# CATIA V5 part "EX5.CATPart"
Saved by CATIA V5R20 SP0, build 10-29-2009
Part number: EX5
Bounding box of the stored display mesh (mm): x -50 to 70, y -49.602 to 49.945, z 0 to 10
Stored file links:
  E:\Nouveau dossier\tarek\mécaniquee\Catia\TP 0\EX5.CATPart
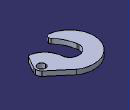
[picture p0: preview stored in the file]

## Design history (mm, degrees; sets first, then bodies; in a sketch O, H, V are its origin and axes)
Set1
  DatumSurface1 to DatumSurface15
Body1 (main body)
